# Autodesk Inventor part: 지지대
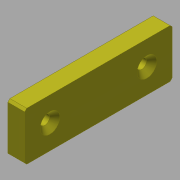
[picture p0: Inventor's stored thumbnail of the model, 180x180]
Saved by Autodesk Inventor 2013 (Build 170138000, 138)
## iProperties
Created: 2017-04
Part Number: 지지대
Material: 강철
Document SubType Name: Modeling
Designer: mduedu
Density: 7.85 g/cm^3
Mass: 98.0769 g
Surface Area: 48.2288 cm^2
Volume: 12.4939 cm^3
Author: mduedu
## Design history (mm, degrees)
sketch "스케치1"
  geometry: L1 (23, -35)-(23, 35); L2 (0, -35)-(0, 35); L3 (0, 35)-(23, 35); L4 (0, -35)-(23, -35); 2 further points
  constraints: 8 end point, 2 parallel, 1 coincident, 1 midpoint, 1 perpendicular, 1 vertical
  dimensions: "d1" = 23 distance between parallel lines of L2 L1; "d15" = 70 distance of L1.start L1.end
extrude "돌출1" new body sketch "스케치1" distance "d2" = 8; taper "d3" = 0 deg
chamfer "모따기2" distance "d16" = 1; stored, may be unused: second distance "d17" = 2, angle "d18" = 45 deg
sketch "스케치2"
  geometry: L1 (1, -35)-(22, -35) reference; L2 (23, -34)-(23, 34) reference; L3 (22, 35)-(1, 35) reference; L4 (0, 34)-(0, -34) reference; L5 (11.5, 35)-(11.5, -35); L6 (23, 0)-(0, 0); L7 (1, -35)-(0, -34) reference; L8 (23, -34)-(22, -35) reference; L9 (22, 35)-(23, 34) reference; L10 (0, 34)-(1, 35) reference; 2 further points
  constraints: 4 end point, 4 midpoint, 1 point on line, 1 symmetric about line
  dimensions: "d7" = 12 distance from line of point (11.5, 23) L3
  node "투영된 루프1"
sketch "스케치3"
  geometry: 4 further points
  constraints: 2 coincident
hole "구멍1" sketch "스케치3" at (11.5, 23), (11.5, -23) diameter "d8" = 4.5; stored, may be unused: countersink angle "d12" = 90 deg, drill point angle "d14" = 0 deg; dims "d9" = 6, "d10" = 9.4, "d11" = 2, "d13" = 8
node "솔리드2"
node "솔리드1"
